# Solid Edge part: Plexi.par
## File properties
Author: Krammer
Template: iso metric part.par
Last saved by: Krammer
Revision: 2
Application: Solid Edge
Accuracy: 0,990
Username: Krammer
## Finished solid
Body 1: solid body, 6 faces, 12 edges, 8 vertices.
  Faces by surface: plane 6
  Edges by curve: line 12
Bounding box of the edges (mm): 5.000 x 11.000 x 0.500, from (-2.5, -5.5, 0) to (2.5, 5.5, 0.5).
Planar faces by outward normal: +x 1, +y 1, +z 1, -x 1, -y 1, -z 1
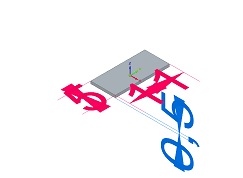
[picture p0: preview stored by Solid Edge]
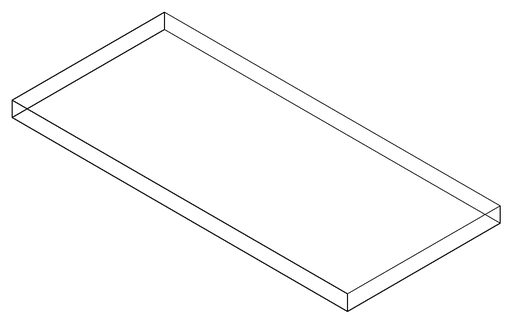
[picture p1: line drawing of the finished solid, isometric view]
